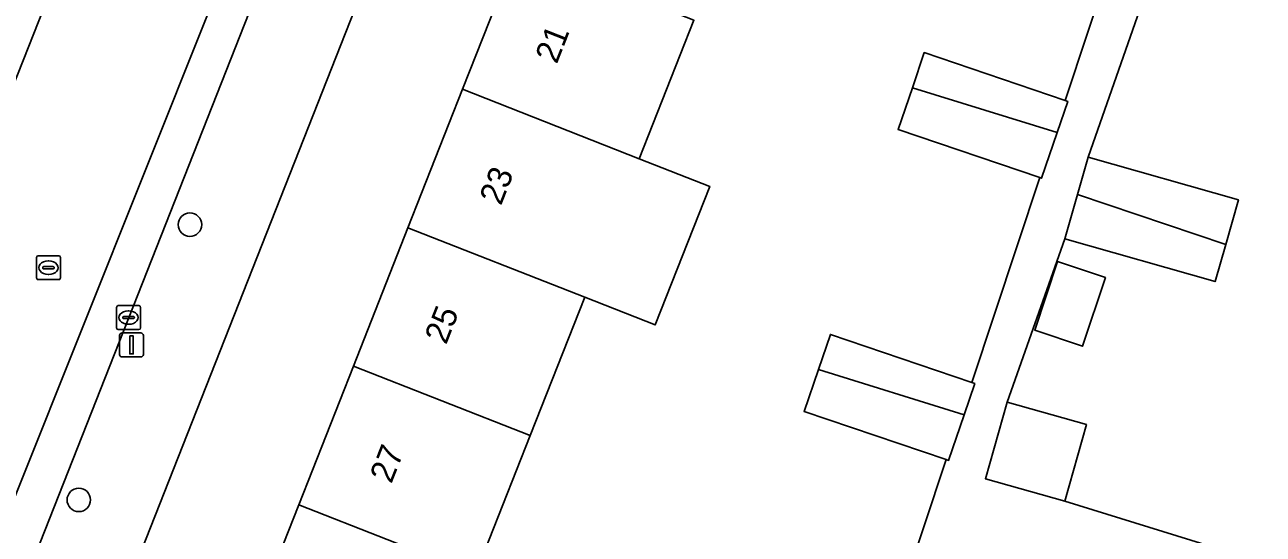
# Model space of a CAD drawing. Extents: x 159817 to 160765, y 380688 to 381638.
# Drawn here: x 160299.4 to 160351, y 381269.5 to 381290.8 of the extents above; entities that cross this region are included whole.
import ezdxf

# ---------------------------------------------------------------- set-up
doc = ezdxf.new("R2010")
doc.units = 0
for name, color, linetype in [('IMGEO_Boom', 7, 'Continuous'), ('IMGEO_Erf', 7, 'Continuous'), ('IMGEO_Kolk', 7, 'Continuous'), ('IMGEO_Lichtmast', 7, 'Continuous'), ('IMGEO_Pand', 7, 'Continuous'), ('IMGEO_Pand_nummerreeks', 7, 'Continuous'), ('IMGEO_Parkeervlak_open', 7, 'Continuous'), ('IMGEO_Rijbaan_lokaal_open', 7, 'Continuous'), ('IMGEO_Rioolput', 7, 'Continuous'), ('IMGEO_Voetpad_open', 7, 'Continuous')]:
    doc.layers.add(name, color=color, linetype=linetype)

msp = doc.modelspace()

# ---------------------------------------------------------------- linework, layer by layer
at = {"layer": 'IMGEO_Boom'}
for centre in [(160306.264, 381282.43), (160301.629, 381270.936)]:
    msp.add_circle(centre, 0.489, dxfattribs=at)
at = {"layer": 'IMGEO_Erf'}
for points in [[(160315.356, 381282.301), (160317.632, 381288.082), (160319.908, 381293.863), (160322.183, 381299.644), (160324.459, 381305.426), (160326.734, 381311.206), (160329.054, 381317.099), (160324.255, 381319.059), (160316.635, 381300.299), (160303.457, 381266.825), (160308.485, 381264.845), (160310.805, 381270.738), (160313.08, 381276.519)], [(160343.491, 381277.356), (160341.491, 381278.019), (160342.442, 381280.886), (160344.442, 381280.223)]]:
    msp.add_lwpolyline(points, close=True, dxfattribs=at)
for points in [[(160334.971, 381264.072), (160337.801, 381272.618), (160331.878, 381274.634), (160332.472, 381276.38), (160332.97, 381277.844), (160338.867, 381275.837), (160341.7, 381284.393), (160335.797, 381286.401), (160336.392, 381288.149), (160336.889, 381289.611), (160342.766, 381287.612), (160345.618, 381296.224)], [(160352.725, 381291.306), (160346.462, 381293.095), (160343.724, 381285.25), (160349.987, 381283.46), (160349.458, 381281.607), (160349.014, 381280.053), (160342.751, 381281.843), (160340.343, 381275.021), (160343.65, 381274.086), (160342.746, 381270.888), (160353.846, 381267.453)], [(160327.28, 381290.965), (160325.004, 381285.183), (160327.944, 381284.025), (160325.668, 381278.245), (160322.728, 381279.403), (160320.452, 381273.621), (160318.176, 381267.839)]]:
    msp.add_lwpolyline(points, dxfattribs=at)
at = {"layer": 'IMGEO_Kolk'}
for p, q in [((160303.202, 381278.125), (160303.202, 381278.977)), ((160303.277, 381279.051), (160304.129, 381279.051)), ((160303.69, 381278.831), (160303.715, 381278.831)), ((160304.203, 381278.977), (160304.203, 381278.125)), ((160303.461, 381278.545), (160303.461, 381278.557)), ((160303.899, 381278.508), (160303.501, 381278.508)), ((160303.504, 381278.594), (160303.902, 381278.594)), ((160303.713, 381278.271), (160303.688, 381278.271)), ((160303.945, 381278.557), (160303.945, 381278.545)), ((160304.129, 381278.051), (160303.277, 381278.051))]:
    msp.add_line(p, q, dxfattribs=at)
for points in [[(160303.202, 381278.125), (160303.202, 381278.977)], [(160303.277, 381279.051), (160304.129, 381279.051)], [(160304.203, 381278.977), (160304.203, 381278.125)], [(160304.129, 381278.051), (160303.277, 381278.051)]]:
    msp.add_lwpolyline(points, dxfattribs=at)
for centre, radius, start, end in [((160303.279, 381278.975), 0.0765, 91.552, 178.448), ((160303.279, 381278.975), 0.0765, 91.552, 178.448), ((160304.127, 381278.975), 0.0765, 1.552, 88.448), ((160304.127, 381278.975), 0.0765, 1.552, 88.448), ((160303.501, 381278.554), 0.0403, 85.8775, 175.7526), ((160303.498, 381278.544), 0.0366, 178.938, 274.7102), ((160303.902, 381278.551), 0.043, 264.8664, 352.4533), ((160303.906, 381278.556), 0.0386, 1.7309, 96.639), ((160303.279, 381278.127), 0.0765, 181.552, 268.448), ((160303.279, 381278.127), 0.0765, 181.552, 268.448), ((160304.127, 381278.127), 0.0765, 271.552, 358.448), ((160304.127, 381278.127), 0.0765, 271.552, 358.448)]:
    msp.add_arc(centre, radius, start, end, dxfattribs=at)
for centre, major_axis, ratio, start_param, end_param in [((160303.689, 381278.551), (-0.387, 0.002), 0.722429, 4.712389, 7.853982), ((160303.714, 381278.551), (-0.39, 0.002), 0.717154, 1.570796, 4.712389)]:
    msp.add_ellipse(centre, major_axis=major_axis, ratio=ratio, start_param=start_param, end_param=end_param, dxfattribs=at)
at = {"layer": 'IMGEO_Lichtmast'}
for p, q in [((160303.331, 381277.006), (160303.331, 381277.806)), ((160303.331, 381277.806), (160303.331, 381277.006)), ((160303.431, 381277.906), (160304.221, 381277.906)), ((160304.221, 381277.906), (160303.431, 381277.906)), ((160304.321, 381277.806), (160304.321, 381277.006)), ((160304.321, 381277.006), (160304.321, 381277.806)), ((160304.221, 381276.906), (160303.431, 381276.906)), ((160303.431, 381276.906), (160304.221, 381276.906))]:
    msp.add_line(p, q, dxfattribs=at)
msp.add_lwpolyline([(160303.751, 381277.781), (160303.901, 381277.781), (160303.901, 381277.031), (160303.751, 381277.031), (160303.751, 381277.781)], dxfattribs=at)
for centre, start, end in [((160303.431, 381277.806), 90, 180), ((160303.431, 381277.806), 90, 180), ((160304.221, 381277.806), 0, 90), ((160304.221, 381277.806), 360, 90), ((160303.431, 381277.006), 180, 270), ((160303.431, 381277.006), 180, 270), ((160304.221, 381277.006), 270, 0), ((160304.221, 381277.006), 270, 0)]:
    msp.add_arc(centre, 0.1, start, end, dxfattribs=at)
at = {"layer": 'IMGEO_Pand'}
for points in [[(160325.004, 381285.183), (160327.28, 381290.965), (160319.908, 381293.863), (160317.632, 381288.082)], [(160336.889, 381289.611), (160336.392, 381288.149), (160342.428, 381286.278), (160342.869, 381287.577), (160342.766, 381287.612)], [(160325.004, 381285.183), (160317.632, 381288.082), (160315.356, 381282.301), (160322.728, 381279.403), (160325.668, 381278.245), (160327.944, 381284.025)], [(160342.428, 381286.278), (160336.392, 381288.149), (160335.797, 381286.401), (160341.7, 381284.393), (160341.778, 381284.367)], [(160343.278, 381283.685), (160349.458, 381281.607), (160349.987, 381283.46), (160343.724, 381285.25)], [(160343.278, 381283.685), (160342.751, 381281.843), (160349.014, 381280.053), (160349.458, 381281.607)], [(160320.452, 381273.621), (160322.728, 381279.403), (160315.356, 381282.301), (160313.08, 381276.519)], [(160341.491, 381278.019), (160343.491, 381277.356), (160344.442, 381280.223), (160342.442, 381280.886)], [(160332.97, 381277.844), (160332.472, 381276.38), (160338.553, 381274.494), (160338.995, 381275.793), (160338.867, 381275.837)], [(160320.452, 381273.621), (160313.08, 381276.519), (160310.805, 381270.738), (160318.176, 381267.839)], [(160338.553, 381274.494), (160332.472, 381276.38), (160331.878, 381274.634), (160337.801, 381272.618), (160337.903, 381272.583)], [(160343.65, 381274.086), (160340.343, 381275.021), (160339.439, 381271.822), (160342.746, 381270.888)], [(160318.176, 381267.839), (160310.805, 381270.738), (160308.485, 381264.845), (160313.138, 381263.013), (160315.855, 381261.943)]]:
    msp.add_lwpolyline(points, close=True, dxfattribs=at)
at = {"layer": 'IMGEO_Parkeervlak_open'}
for points in [[(160316.946, 381316.648), (160307.058, 381291.325), (160299.09, 381271.369), (160281.271, 381226.443), (160275.014, 381208.821)], [(160277.458, 381210.919), (160277.528, 381211.127), (160278.579, 381214.023), (160280.449, 381219.18), (160283.742, 381227.747), (160288.666, 381240.388), (160288.992, 381241.225), (160292.45, 381250), (160312.413, 381300.657)]]:
    msp.add_lwpolyline(points, dxfattribs=at)
at = {"layer": 'IMGEO_Rijbaan_lokaal_open'}
msp.add_lwpolyline([(160281.271, 381226.443), (160299.09, 381271.369), (160307.058, 381291.325), (160316.946, 381316.648), (160311.054, 381318.986), (160304.324, 381302.023), (160283.79, 381250), (160281.212, 381243.47), (160281.107, 381243.114), (160275.368, 381228.672), (160275.08, 381227.786), (160271.695, 381219.129), (160267.546, 381205.381), (160267.463, 381204.669), (160266.535, 381197.216)], dxfattribs=at)
at = {"layer": 'IMGEO_Rioolput'}
for p, q in [((160299.864, 381280.207), (160299.864, 381281.059)), ((160299.939, 381281.133), (160300.791, 381281.133)), ((160300.352, 381280.913), (160300.377, 381280.913)), ((160300.865, 381281.059), (160300.865, 381280.207)), ((160300.123, 381280.627), (160300.123, 381280.639)), ((160300.561, 381280.59), (160300.163, 381280.59)), ((160300.166, 381280.676), (160300.564, 381280.676)), ((160300.375, 381280.353), (160300.35, 381280.353)), ((160300.607, 381280.639), (160300.607, 381280.627)), ((160300.791, 381280.133), (160299.939, 381280.133))]:
    msp.add_line(p, q, dxfattribs=at)
for points in [[(160299.864, 381280.207), (160299.864, 381281.059)], [(160299.939, 381281.133), (160300.791, 381281.133)], [(160300.865, 381281.059), (160300.865, 381280.207)], [(160300.791, 381280.133), (160299.939, 381280.133)]]:
    msp.add_lwpolyline(points, dxfattribs=at)
for centre, radius, start, end in [((160299.941, 381281.057), 0.0765, 91.552, 178.448), ((160299.941, 381281.057), 0.0765, 91.552, 178.448), ((160300.789, 381281.057), 0.0765, 1.552, 88.448), ((160300.789, 381281.057), 0.0765, 1.552, 88.448), ((160300.163, 381280.636), 0.0403, 85.8775, 175.7526), ((160300.16, 381280.626), 0.0366, 178.938, 274.7102), ((160300.564, 381280.633), 0.043, 264.8664, 352.4533), ((160300.568, 381280.638), 0.0386, 1.7309, 96.639), ((160299.941, 381280.209), 0.0765, 181.552, 268.448), ((160299.941, 381280.209), 0.0765, 181.552, 268.448), ((160300.789, 381280.209), 0.0765, 271.552, 358.448), ((160300.789, 381280.209), 0.0765, 271.552, 358.448)]:
    msp.add_arc(centre, radius, start, end, dxfattribs=at)
for centre, major_axis, ratio, start_param, end_param in [((160300.351, 381280.633), (-0.387, 0.002), 0.722429, 4.712389, 7.853982), ((160300.376, 381280.633), (-0.39, 0.002), 0.717154, 1.570796, 4.712389)]:
    msp.add_ellipse(centre, major_axis=major_axis, ratio=ratio, start_param=start_param, end_param=end_param, dxfattribs=at)
at = {"layer": 'IMGEO_Voetpad_open'}
for points in [[(160281.212, 381243.47), (160283.79, 381250), (160304.324, 381302.023), (160311.054, 381318.986), (160324.621, 381353.178), (160325.632, 381355.733), (160325.775, 381356.504), (160325.752, 381356.962), (160325.818, 381357.454), (160331.894, 381372.811)], [(160317.479, 381313.129), (160317.409, 381312.956), (160316.641, 381310.994), (160315.493, 381308.263), (160312.413, 381300.657), (160292.45, 381250), (160288.992, 381241.225), (160288.666, 381240.388), (160283.742, 381227.747), (160280.449, 381219.18), (160278.579, 381214.023), (160280.923, 381213.109), (160282.201, 381212.828), (160292.437, 381238.829), (160296.834, 381250), (160302.836, 381265.248), (160303.457, 381266.825), (160316.635, 381300.299)], [(160345.618, 381296.224), (160342.766, 381287.612), (160342.869, 381287.577), (160342.428, 381286.278), (160341.778, 381284.367), (160341.7, 381284.393), (160338.867, 381275.837), (160338.995, 381275.793), (160338.553, 381274.494), (160337.903, 381272.583), (160337.801, 381272.618), (160334.971, 381264.072)], [(160353.846, 381267.453), (160342.746, 381270.888), (160339.439, 381271.822), (160340.343, 381275.021), (160342.751, 381281.843), (160343.278, 381283.685), (160343.724, 381285.25), (160346.462, 381293.095)]]:
    msp.add_lwpolyline(points, dxfattribs=at)

# ---------------------------------------------------------------- texts
at = {"layer": 'IMGEO_Pand_nummerreeks'}
for s, rotation, p in [('21', 68.5137, (160321.561, 381289.107)), ('23', 68.5143, (160319.234, 381283.195)), ('25', 68.5137, (160316.948, 381277.39)), ('27', 68.5137, (160314.663, 381271.584))]:
    msp.add_text(s, height=1, rotation=rotation, dxfattribs=at).set_placement(p)

doc.saveas('drawing.dxf')
